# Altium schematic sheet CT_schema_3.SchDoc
size 283 x 174 mm
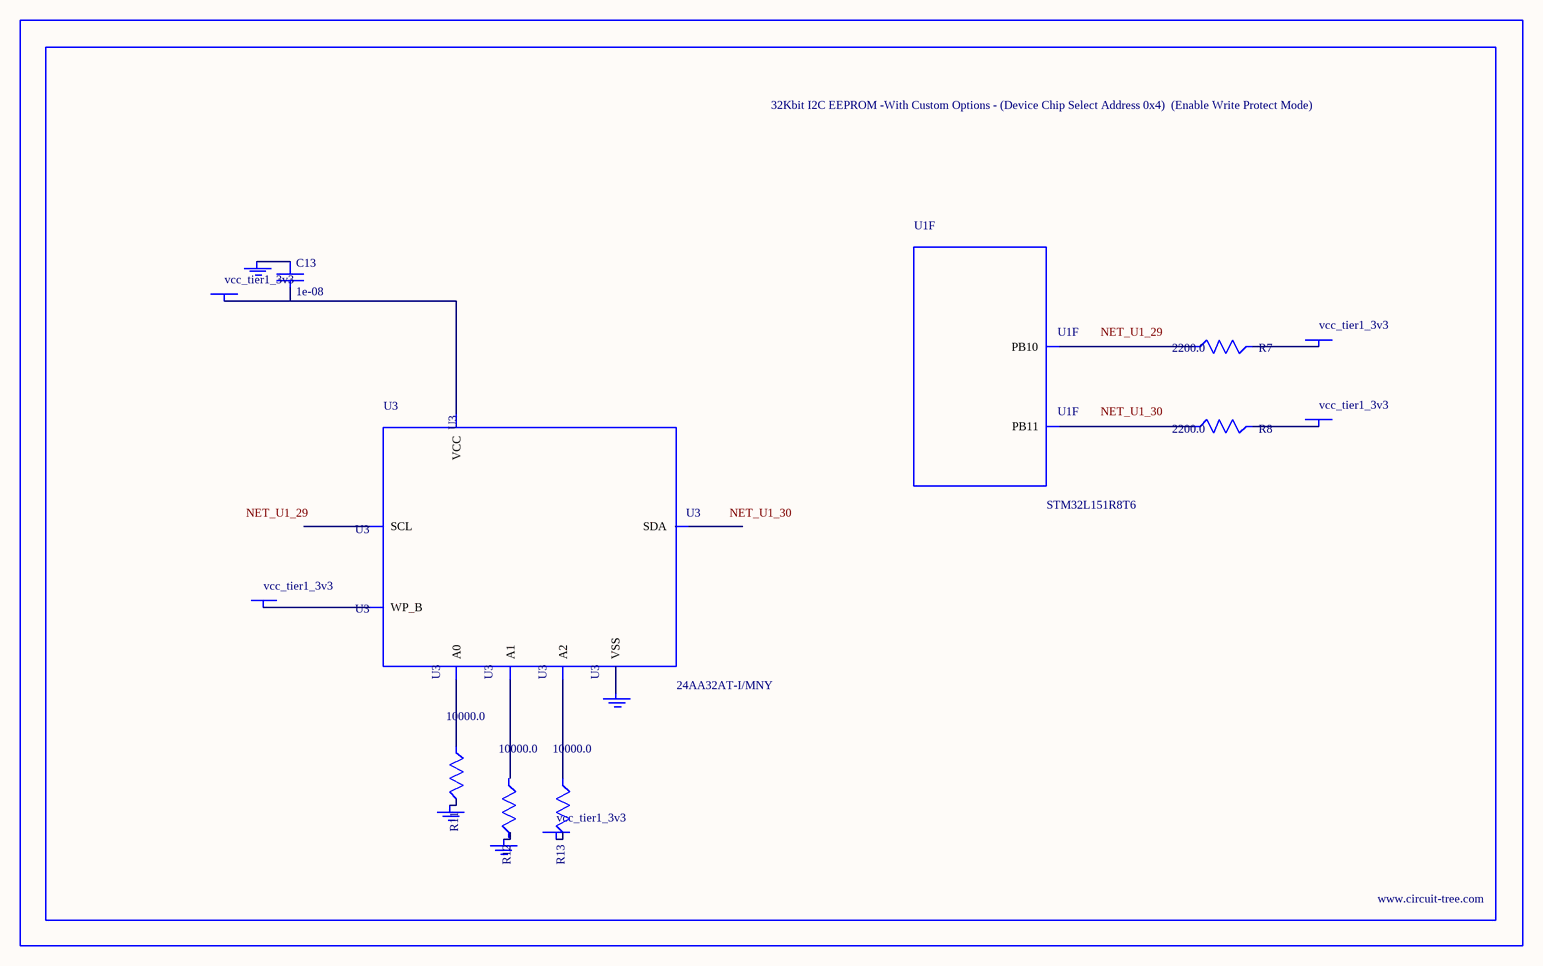
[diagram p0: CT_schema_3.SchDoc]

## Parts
BORDER2  (no value)
C13  1e-08  [C0402]
GND_INSTANCE_2_0  (no value)
GND_INSTANCE_2_1  (no value)
GND_INSTANCE_2_2  (no value)
GND_INSTANCE_2_3  (no value)
POWER_INSTANCE_2_0  vcc_tier1_3v3
POWER_INSTANCE_2_1  vcc_tier1_3v3
POWER_INSTANCE_2_2  vcc_tier1_3v3
POWER_INSTANCE_2_3  vcc_tier1_3v3
POWER_INSTANCE_2_4  vcc_tier1_3v3
R7  2200.0  [R0603]
R8  2200.0  [R0603]
R11  10000.0  [R0603]
R12  10000.0  [R0603]
R13  10000.0  [R0603]
U1  STM32L151R8T6  [LQFP64]  (part F of 7)
U3  24AA32AT-I/MNY  [TDFN-8/6MM]

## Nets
NetC13_1: C13.1 GND_INSTANCE_2_2.0(GND)
NetC13_2: C13.2 POWER_INSTANCE_2_2.0(PWR) U3.8(VCC)
NetGND_INSTANCE_2_0_0: GND_INSTANCE_2_0.0(GND) R11.2
NetGND_INSTANCE_2_3_0: GND_INSTANCE_2_3.0(GND) U3.4(VSS)
NetPOWER_INSTANCE_2_0_0: POWER_INSTANCE_2_0.0(PWR) R13.2
NetPOWER_INSTANCE_2_1_0: POWER_INSTANCE_2_1.0(PWR) U3.7(WP_B)
NetPOWER_INSTANCE_2_3_0: POWER_INSTANCE_2_3.0(PWR) R7.2
NetPOWER_INSTANCE_2_4_0: POWER_INSTANCE_2_4.0(PWR) R8.2
NetR7_1: R7.1 U1.29(PB10)
NetR8_1: R8.1 U1.30(PB11)
NetR11_1: R11.1 U3.1(A0)
NetR13_1: R13.1 U3.3(A2)

Not connected (* = marked no-connect by the designer): GND_INSTANCE_2_1 0(GND); R12 1 2; U3 2(A1) 5(SDA) 6(SCL)

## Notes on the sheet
- Labels drawn without touching a wire or pin: NET_U1_29, NET_U1_30

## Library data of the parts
BORDER2 = BORDER_PAGE2
C13 = C0402C103K3RAC
GND_INSTANCE_2_0-GND_INSTANCE_2_3 = GND
POWER_INSTANCE_2_0-POWER_INSTANCE_2_4 = PWR
R7 R8 = RC0603JR-072K2L
R11-R13 = RC0603JR-0710KL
